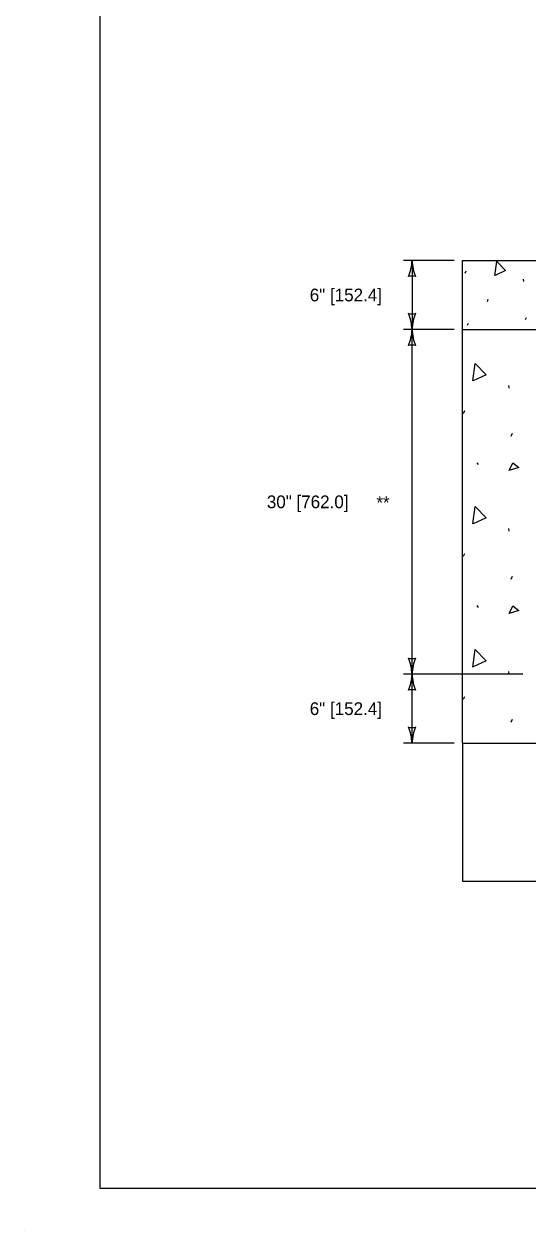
# Model space of a CAD drawing. Extents: x 49991.4 to 50057, y 49987.6 to 50011.4.
# Drawn here: x 49999.02 to 50001.4, y 49987.6 to 49993.29 of the extents above; entities that cross this region are included whole.
import ezdxf

# ---------------------------------------------------------------- set-up
doc = ezdxf.new("R2010")
doc.units = 0
for name, color, linetype in [('Level 1', 7, 'Continuous'), ('Level 2', 7, 'Continuous'), ('Level 3', 7, 'Continuous'), ('Level 4', 7, 'Continuous')]:
    doc.layers.add(name, color=color, linetype=linetype)

msp = doc.modelspace()

# ---------------------------------------------------------------- linework, layer by layer
at = {"layer": 'Level 1'}
for p, q in [((50001.0929, 49992.1729), (50002.0679, 49992.1729)), ((50001.0929, 49989.8979), (50001.0929, 49992.1729)), ((50001.105, 49992.1138), (50001.1096, 49992.1242)), ((50001.3794, 49992.0848), (50001.3806, 49992.0744)), ((50001.21, 49991.9799), (50001.2146, 49991.9903)), ((50001.1165, 49991.8678), (50001.1211, 49991.8782)), ((50001.3901, 49991.8943), (50001.3947, 49991.9047)), ((50001.0929, 49991.8479), (50002.0679, 49991.8479)), ((50001.3094, 49991.5837), (50001.3108, 49991.5707)), ((50001.0976, 49991.4525), (50001.1034, 49991.4655)), ((50001.3227, 49991.3456), (50001.3285, 49991.3586)), ((50001.1611, 49991.22), (50001.1669, 49991.2114)), ((50001.3094, 49990.9096), (50001.3108, 49990.8966)), ((50001.0976, 49990.7785), (50001.1034, 49990.7915)), ((50001.3227, 49990.6715), (50001.3285, 49990.6845)), ((50001.1611, 49990.546), (50001.1669, 49990.5373)), ((50001.3094, 49990.2355), (50001.3108, 49990.2226)), ((50001.0976, 49990.1044), (50001.1034, 49990.1174)), ((50001.3227, 49989.9974), (50001.3285, 49990.0104)), ((50001.0929, 49989.8979), (50004.3429, 49989.8979)), ((50001.0929, 49989.8979), (50001.0929, 49989.8979)), ((49999.0245, 49987.5988), (49999.0245, 49987.5988))]:
    msp.add_line(p, q, dxfattribs=at)
msp.add_lwpolyline([(49999.3835, 49998.9992), (50016.7501, 49998.9992), (50016.7501, 49987.7988), (49999.3835, 49987.7988)], close=True, dxfattribs=at)
for points in [[(50001.2454, 49992.1019), (50001.2546, 49992.1678), (50001.2959, 49992.1252), (50001.2465, 49992.1023)], [(50001.1419, 49991.605), (50001.1533, 49991.6875), (50001.205, 49991.6341), (50001.1432, 49991.6055)], [(50001.3126, 49991.1825), (50001.3299, 49991.2186), (50001.3588, 49991.1969), (50001.3126, 49991.1825)], [(50001.1419, 49990.9309), (50001.1533, 49991.0134), (50001.205, 49990.96), (50001.1432, 49990.9314)], [(50001.3126, 49990.5084), (50001.3299, 49990.5445), (50001.3588, 49990.5229), (50001.3126, 49990.5084)], [(50001.1419, 49990.2568), (50001.1533, 49990.3393), (50001.205, 49990.286), (50001.1432, 49990.2573)]]:
    msp.add_lwpolyline(points, dxfattribs=at)
at = {"layer": 'Level 3'}
for p, q in [((50001.0529, 49992.1729), (50000.8147, 49992.1729)), ((50000.8547, 49992.1729), (50000.8547, 49991.8479)), ((50001.0529, 49991.8479), (50000.8147, 49991.8479)), ((50000.8547, 49990.2229), (50000.8547, 49991.8479)), ((50001.3779, 49990.2229), (50000.8147, 49990.2229)), ((50000.8547, 49989.8979), (50000.8547, 49990.2229)), ((50001.0529, 49989.8979), (50000.8147, 49989.8979))]:
    msp.add_line(p, q, dxfattribs=at)
for centre, radius, start, end in [((50000.6326, 49992.1821), 0.2223, 337.456, 357.6395), ((50001.0874, 49992.1844), 0.233, 182.8273, 202.0772), ((50000.8547, 49992.0447), 0.0548, 72.1388, 107.8612), ((50000.8547, 49991.9761), 0.0548, 252.1388, 287.8612), ((50000.622, 49991.8364), 0.233, 2.8273, 22.0772), ((50001.0768, 49991.8388), 0.2223, 157.456, 177.6395), ((50000.6326, 49991.8571), 0.2223, 337.456, 357.6395), ((50001.0874, 49991.8594), 0.233, 182.8273, 202.0772), ((50000.8547, 49991.7197), 0.0548, 72.1388, 107.8612), ((50000.8547, 49990.3511), 0.0548, 252.1388, 287.8612), ((50000.622, 49990.2114), 0.233, 2.8273, 22.0772), ((50001.0768, 49990.2138), 0.2223, 157.456, 177.6395), ((50000.6326, 49990.2321), 0.2223, 337.456, 357.6395), ((50001.0874, 49990.2344), 0.233, 182.8273, 202.0772), ((50000.8547, 49990.0947), 0.0548, 72.1388, 107.8612), ((50000.8547, 49990.0261), 0.0548, 252.1388, 287.8612), ((50000.622, 49989.8864), 0.233, 2.8273, 22.0772), ((50001.0768, 49989.8888), 0.2223, 157.456, 177.6395)]:
    msp.add_arc(centre, radius, start, end, dxfattribs=at)
at = {"layer": 'Level 4'}
for p, q in [((50001.0929, 49989.8979), (50001.0929, 49989.5729)), ((50001.0929, 49989.5729), (50001.0929, 49989.2479)), ((50001.0929, 49989.2479), (50004.3429, 49989.2479))]:
    msp.add_line(p, q, dxfattribs=at)

# ---------------------------------------------------------------- texts
at = {"layer": 'Level 2'}
for s, p in [('6" [152.4]', (50000.3722, 49991.9804)), ('30" [762.0]', (50000.1696, 49991.0054)), ('**', (50000.6865, 49991.0016)), ('6" [152.4]', (50000.3722, 49990.0304))]:
    msp.add_text(s, height=0.06, dxfattribs=at).set_placement(p)

doc.saveas('drawing.dxf')
